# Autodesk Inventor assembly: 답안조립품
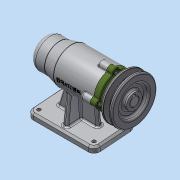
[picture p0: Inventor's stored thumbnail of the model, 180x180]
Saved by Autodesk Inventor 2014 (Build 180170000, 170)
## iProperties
Created: 2019-07
Part Number: 답안조립품
Document SubType Name: Assembly
Designer: kb542-23
Author: kb542-23
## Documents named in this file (12)
- C:\Users\kb542-23\Desktop\490704V1057\답안조립품.iam
- C:\Users\kb542-23\Desktop\490704V1057\본체.ipt
- C:\Users\kb542-23\Desktop\490704V1057\V벨트풀리.ipt
- C:\Users\kb542-23\Desktop\490704V1057\멈춤나사 M3.ipt
- C:\Users\kb542-23\Desktop\490704V1057\베어링 6004.ipt
- C:\Users\kb542-23\Desktop\490704V1057\베어링 51202.ipt
- C:\Users\kb542-23\Desktop\490704V1057\볼트 M4.ipt
- C:\Users\kb542-23\Desktop\490704V1057\어댑터슬리브.ipt
- C:\Users\kb542-23\Desktop\490704V1057\오일 실.ipt
- C:\Users\kb542-23\Desktop\490704V1057\축.ipt
- C:\Users\kb542-23\Desktop\490704V1057\커버.ipt
- C:\Users\kb542-23\Desktop\490704V1057\키 5 x 5 x 16.ipt
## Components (1 placed, 1 different names)
1. V벨트풀리:1
